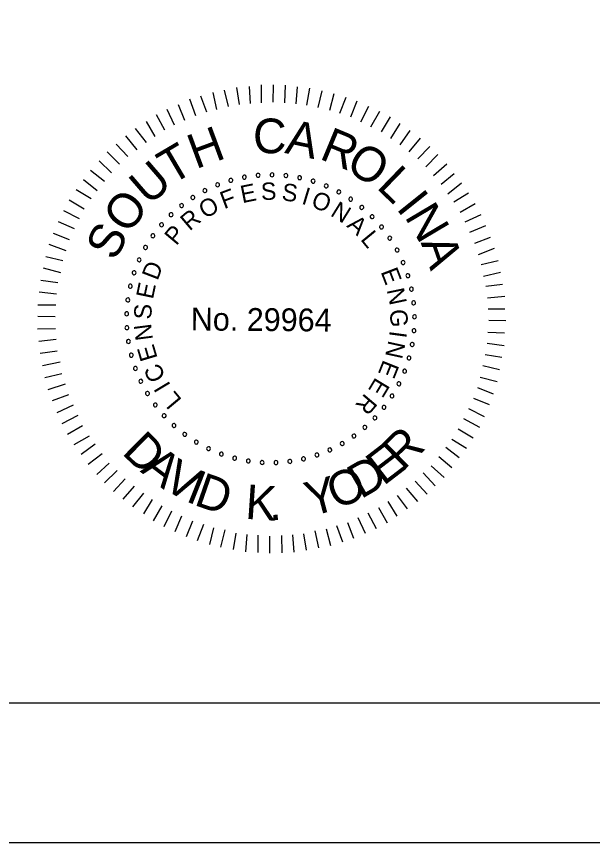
# Model space of a CAD drawing. Extents: x -125.5 to -89.3, y 42.4 to 64.4.
# Drawn here: x -102.136 to -100.072, y 42.449 to 45.407 of the extents above; entities that cross this region are included whole.
import ezdxf

# ---------------------------------------------------------------- set-up
doc = ezdxf.new("R2010")
doc.units = 0
for name, color, linetype in [('BR_BORDER LINES', 7, 'Continuous'), ('BR_TEXT', 7, 'Continuous'), ('Level 31', 7, 'Continuous')]:
    doc.layers.add(name, color=color, linetype=linetype)

msp = doc.modelspace()

# ---------------------------------------------------------------- linework, layer by layer
at = {"layer": 'BR_BORDER LINES'}
msp.add_line((-123.6994, 42.9486), (-90.0334, 42.9486), dxfattribs=at)
at = {"layer": 'BR_TEXT'}
for p, q in [((-101.3372, 45.0917), (-101.3461, 45.1527)), ((-101.2977, 45.0957), (-101.3015, 45.1567)), ((-101.2582, 45.098), (-101.2576, 45.1623)), ((-101.2161, 45.1002), (-101.2156, 45.162)), ((-101.1741, 45.0973), (-101.1718, 45.1616)), ((-101.1338, 45.0944), (-101.129, 45.1552)), ((-101.0952, 45.0897), (-101.0844, 45.1506)), ((-101.4541, 45.0644), (-101.476, 45.122)), ((-101.418, 45.0744), (-101.4312, 45.1354)), ((-101.3767, 45.0843), (-101.3908, 45.1437)), ((-101.0549, 45.0817), (-101.0407, 45.1408)), ((-101.0138, 45.071), (-100.9979, 45.1318)), ((-100.977, 45.0605), (-100.9551, 45.1177)), ((-101.5325, 45.035), (-101.556, 45.091)), ((-101.4937, 45.0518), (-101.5147, 45.1104)), ((-100.9376, 45.0472), (-100.9157, 45.1054)), ((-100.9017, 45.0298), (-100.8738, 45.0853)), ((-101.5695, 45.0181), (-101.5957, 45.0741)), ((-100.8658, 45.0123), (-100.8345, 45.0678)), ((-101.6394, 44.9767), (-101.6698, 45.031)), ((-101.604, 45.0004), (-101.6344, 45.0547)), ((-100.8282, 44.994), (-100.796, 45.0478)), ((-101.6704, 44.9555), (-101.7095, 45.0064)), ((-100.795, 44.9697), (-100.761, 45.0235)), ((-100.7617, 44.948), (-100.7252, 44.9983)), ((-101.7041, 44.93), (-101.744, 44.9801)), ((-100.7293, 44.922), (-100.6886, 44.9714)), ((-101.7369, 44.9054), (-101.7786, 44.9503)), ((-100.6977, 44.8968), (-100.6545, 44.941)), ((-101.7663, 44.8782), (-101.8106, 44.9223)), ((-100.6697, 44.8691), (-100.6264, 44.9125)), ((-101.7958, 44.8475), (-101.8392, 44.8899)), ((-100.6416, 44.838), (-100.594, 44.8796)), ((-101.8209, 44.816), (-101.8704, 44.855)), ((-101.8469, 44.7827), (-101.8964, 44.8226)), ((-100.6144, 44.806), (-100.5677, 44.8442)), ((-100.5906, 44.7723), (-100.5414, 44.8114)), ((-101.8686, 44.7537), (-101.9224, 44.7868)), ((-100.5686, 44.743), (-100.516, 44.7752)), ((-101.893, 44.717), (-101.9467, 44.7492)), ((-100.5466, 44.7059), (-100.4931, 44.7372)), ((-101.9104, 44.6828), (-101.9668, 44.7107)), ((-101.9279, 44.6461), (-101.9851, 44.6714)), ((-100.5288, 44.6714), (-100.4711, 44.6984)), ((-100.5111, 44.6344), (-100.4542, 44.6588)), ((-101.9454, 44.6076), (-102.0035, 44.6295)), ((-100.4943, 44.5956), (-100.4374, 44.6166)), ((-101.9577, 44.5674), (-102.0193, 44.5902)), ((-100.4809, 44.5552), (-100.4232, 44.577)), ((-101.97, 44.5314), (-102.0308, 44.5465)), ((-100.4708, 44.519), (-100.4107, 44.5331)), ((-101.9772, 44.4894), (-102.0397, 44.5054)), ((-100.4626, 44.4769), (-100.4024, 44.4919)), ((-101.9878, 44.4535), (-102.0487, 44.4617)), ((-100.4543, 44.4408), (-100.3951, 44.448)), ((-101.9925, 44.4123), (-102.0542, 44.4197)), ((-100.4478, 44.3996), (-100.3868, 44.4059)), ((-101.9954, 44.3729), (-102.0597, 44.3734)), ((-100.4464, 44.3601), (-100.3863, 44.3596)), ((-101.9974, 44.3317), (-102.06, 44.3322)), ((-100.4442, 44.3189), (-100.3833, 44.3184)), ((-101.9961, 44.2888), (-102.0604, 44.2876)), ((-100.4471, 44.276), (-100.3871, 44.2738)), ((-101.9938, 44.2501), (-102.0556, 44.2429)), ((-100.4492, 44.2374), (-100.3883, 44.2292)), ((-101.9898, 44.2089), (-102.0509, 44.2)), ((-101.9799, 44.1693), (-102.0426, 44.1561)), ((-100.4563, 44.1963), (-100.3972, 44.1863)), ((-100.4653, 44.1568), (-100.4053, 44.1426)), ((-101.9733, 44.1272), (-102.0344, 44.1131)), ((-100.4742, 44.1148), (-100.4143, 44.0998)), ((-101.9616, 44.0903), (-102.0236, 44.0693)), ((-101.95, 44.0515), (-102.0085, 44.0306)), ((-100.4848, 44.0781), (-100.4275, 44.0561)), ((-100.4989, 44.0396), (-100.4424, 44.0176)), ((-101.9331, 44.0145), (-101.9908, 43.9875)), ((-100.5163, 44.0028), (-100.4599, 43.9749)), ((-101.9162, 43.9783), (-101.9731, 43.9487)), ((-100.5346, 43.9669), (-100.4774, 43.9364)), ((-101.8994, 43.9413), (-101.9537, 43.91)), ((-101.8756, 43.9042), (-101.93, 43.8729)), ((-100.553, 43.9301), (-100.5, 43.898)), ((-101.8544, 43.8748), (-101.9045, 43.8383)), ((-100.5756, 43.8934), (-100.5235, 43.8612)), ((-100.5981, 43.8644), (-100.5495, 43.8271)), ((-101.829, 43.8411), (-101.8791, 43.8021)), ((-100.6224, 43.8312), (-100.5764, 43.7913)), ((-101.8043, 43.8075), (-101.8485, 43.7666)), ((-100.6502, 43.7979), (-100.6033, 43.7563)), ((-101.7754, 43.7815), (-101.8204, 43.7364)), ((-100.6787, 43.7724), (-100.6362, 43.7266)), ((-101.7465, 43.7512), (-101.7889, 43.7052)), ((-101.714, 43.7252), (-101.7548, 43.6783)), ((-100.7073, 43.7426), (-100.6648, 43.6959)), ((-101.6808, 43.6992), (-101.7207, 43.6514)), ((-100.7392, 43.7172), (-100.6993, 43.6696)), ((-101.6501, 43.6774), (-101.6814, 43.6254)), ((-100.8057, 43.6705), (-100.7727, 43.6179)), ((-100.772, 43.6917), (-100.7364, 43.6433)), ((-101.6151, 43.6549), (-101.6464, 43.6011)), ((-100.8393, 43.6485), (-100.808, 43.5941)), ((-101.5809, 43.6348), (-101.608, 43.5793)), ((-101.5442, 43.6174), (-101.5687, 43.5618)), ((-100.9134, 43.6122), (-100.8865, 43.5562)), ((-100.8773, 43.629), (-100.8468, 43.573)), ((-101.5057, 43.5999), (-101.5276, 43.5434)), ((-101.4663, 43.5876), (-101.4891, 43.5294)), ((-100.9892, 43.5836), (-100.9682, 43.5251)), ((-100.9496, 43.5953), (-100.9286, 43.5385)), ((-101.4304, 43.5752), (-101.4446, 43.5162)), ((-101.3892, 43.568), (-101.4044, 43.5064)), ((-101.3499, 43.5565), (-101.3598, 43.4983)), ((-101.3104, 43.552), (-101.3152, 43.4902)), ((-101.271, 43.549), (-101.2715, 43.4872)), ((-101.1869, 43.5484), (-101.1857, 43.4865)), ((-101.1465, 43.5506), (-101.1428, 43.4888)), ((-101.1079, 43.5545), (-101.098, 43.4961)), ((-101.0674, 43.5654), (-101.0542, 43.5035)), ((-101.0262, 43.5719), (-101.0112, 43.5126)), ((-101.229, 43.5461), (-101.2295, 43.4852))]:
    msp.add_line(p, q, dxfattribs=at)
for centre, start, end in [((-101.3681, 44.8202), 16.1422, 196.1422), ((-101.3681, 44.8202), 196.1422, 16.1422), ((-101.3196, 44.8316), 10.6038, 190.6038), ((-101.3196, 44.8316), 190.6038, 10.6038), ((-101.2702, 44.8383), 5.0653, 185.0653), ((-101.2702, 44.8383), 185.0653, 5.0653), ((-101.2204, 44.8402), 359.5268, 179.5268), ((-101.2204, 44.8402), 179.5268, 359.5268), ((-101.1707, 44.8373), 173.9884, 353.9884), ((-101.1707, 44.8373), 353.9884, 173.9884), ((-101.1214, 44.8296), 168.4499, 348.4499), ((-101.1214, 44.8296), 348.4499, 168.4499), ((-101.0732, 44.8172), 162.9114, 342.9114), ((-101.0732, 44.8172), 342.9114, 162.9114), ((-101.4607, 44.7836), 27.2191, 207.2191), ((-101.4153, 44.8042), 21.6807, 201.6807), ((-101.4153, 44.8042), 201.6807, 21.6807), ((-101.0263, 44.8002), 157.373, 337.373), ((-101.0263, 44.8002), 337.373, 157.373), ((-101.5039, 44.7588), 32.7576, 212.7576), ((-101.5039, 44.7588), 212.7576, 32.7576), ((-101.4607, 44.7836), 207.2191, 27.2191), ((-100.9814, 44.7787), 151.8345, 331.8345), ((-100.9814, 44.7787), 331.8345, 151.8345), ((-100.9387, 44.753), 326.2961, 146.2961), ((-101.5445, 44.7299), 38.2961, 218.2961), ((-101.5445, 44.7299), 218.2961, 38.2961), ((-100.9387, 44.753), 146.2961, 326.2961), ((-100.8987, 44.7233), 320.7576, 140.7576), ((-101.5821, 44.6973), 43.8345, 223.8345), ((-101.5821, 44.6973), 223.8345, 43.8345), ((-100.8987, 44.7233), 140.7576, 320.7576), ((-100.8617, 44.6899), 135.2191, 315.2191), ((-100.8617, 44.6899), 315.2191, 135.2191), ((-101.6164, 44.6611), 49.373, 229.373), ((-101.6164, 44.6611), 229.373, 49.373), ((-100.8281, 44.6531), 129.6807, 309.6807), ((-100.8281, 44.6531), 309.6807, 129.6807), ((-101.6471, 44.6218), 54.9114, 234.9114), ((-101.6471, 44.6218), 234.9114, 54.9114), ((-100.7983, 44.6132), 124.1422, 304.1422), ((-100.7983, 44.6132), 304.1422, 124.1422), ((-101.6738, 44.5798), 60.4499, 240.4499), ((-101.6738, 44.5798), 240.4499, 60.4499), ((-100.7724, 44.5706), 118.6038, 298.6038), ((-100.7724, 44.5706), 298.6038, 118.6038), ((-101.6964, 44.5354), 65.9884, 245.9884), ((-101.6964, 44.5354), 245.9884, 65.9884), ((-100.7508, 44.5257), 113.0653, 293.0653), ((-100.7508, 44.5257), 293.0653, 113.0653), ((-101.7145, 44.4889), 71.5268, 251.5268), ((-101.7145, 44.4889), 251.5268, 71.5268), ((-100.7336, 44.4789), 107.5268, 287.5268), ((-100.7336, 44.4789), 287.5268, 107.5268), ((-101.7281, 44.441), 77.0653, 257.0653), ((-101.7281, 44.441), 257.0653, 77.0653), ((-100.721, 44.4307), 101.9884, 281.9884), ((-100.721, 44.4307), 281.9884, 101.9884), ((-101.737, 44.392), 82.6038, 262.6038), ((-101.737, 44.392), 262.6038, 82.6038), ((-100.7131, 44.3815), 96.4499, 276.4499), ((-100.7131, 44.3815), 276.4499, 96.4499), ((-101.7411, 44.3423), 88.1422, 268.1422), ((-101.7411, 44.3423), 268.1422, 88.1422), ((-100.71, 44.3317), 90.9114, 270.9114), ((-100.71, 44.3317), 270.9114, 90.9114), ((-101.7404, 44.2925), 93.6807, 273.6807), ((-101.7404, 44.2925), 273.6807, 93.6807), ((-100.7118, 44.2819), 85.373, 265.373), ((-100.7118, 44.2819), 265.373, 85.373), ((-101.7349, 44.243), 99.2191, 279.2191), ((-101.7349, 44.243), 279.2191, 99.2191), ((-100.7183, 44.2325), 79.8345, 259.8345), ((-100.7183, 44.2325), 259.8345, 79.8345), ((-101.7246, 44.1942), 104.7576, 284.7576), ((-101.7246, 44.1942), 284.7576, 104.7576), ((-100.7295, 44.184), 74.2961, 254.2961), ((-100.7295, 44.184), 254.2961, 74.2961), ((-101.7097, 44.1466), 110.2961, 290.2961), ((-101.7097, 44.1466), 290.2961, 110.2961), ((-100.7454, 44.1368), 68.7576, 248.7576), ((-100.7454, 44.1368), 248.7576, 68.7576), ((-101.6903, 44.1008), 115.8345, 295.8345), ((-101.6903, 44.1008), 295.8345, 115.8345), ((-100.7658, 44.0913), 63.2191, 243.2191), ((-100.7658, 44.0913), 243.2191, 63.2191), ((-101.6665, 44.057), 121.373, 301.373), ((-101.6665, 44.057), 301.373, 121.373), ((-100.7904, 44.048), 57.6807, 237.6807), ((-100.7904, 44.048), 237.6807, 57.6807), ((-101.6386, 44.0157), 126.9114, 306.9114), ((-101.6386, 44.0157), 306.9114, 126.9114), ((-100.8192, 44.0073), 52.1422, 232.1422), ((-100.8192, 44.0073), 232.1422, 52.1422), ((-101.6069, 43.9773), 132.4499, 312.4499), ((-101.6069, 43.9773), 312.4499, 132.4499), ((-100.8517, 43.9695), 46.6038, 226.6038), ((-100.8517, 43.9695), 226.6038, 46.6038), ((-101.5716, 43.9421), 137.9884, 317.9884), ((-101.5716, 43.9421), 317.9884, 137.9884), ((-100.8877, 43.9351), 41.0653, 221.0653), ((-100.8877, 43.9351), 221.0653, 41.0653), ((-101.5331, 43.9105), 143.5268, 323.5268), ((-101.5331, 43.9105), 323.5268, 143.5268), ((-100.9269, 43.9043), 35.5268, 215.5268), ((-100.9269, 43.9043), 215.5268, 35.5268), ((-101.4917, 43.8827), 149.0653, 329.0653), ((-101.4917, 43.8827), 329.0653, 149.0653), ((-100.9688, 43.8774), 29.9884, 209.9884), ((-100.9688, 43.8774), 209.9884, 29.9884), ((-101.4478, 43.8591), 154.6038, 334.6038), ((-101.4478, 43.8591), 334.6038, 154.6038), ((-101.4018, 43.8399), 340.1422, 160.1422), ((-101.0595, 43.8364), 18.9114, 198.9114), ((-101.0132, 43.8547), 24.4499, 204.4499), ((-101.0132, 43.8547), 204.4499, 24.4499), ((-101.4018, 43.8399), 160.1422, 340.1422), ((-101.3542, 43.8251), 165.6807, 345.6807), ((-101.3542, 43.8251), 345.6807, 165.6807), ((-101.3054, 43.8151), 351.2191, 171.2191), ((-101.3054, 43.8151), 171.2191, 351.2191), ((-101.2559, 43.8097), 356.7576, 176.7576), ((-101.2061, 43.8092), 2.2961, 182.2961), ((-101.1564, 43.8135), 7.8345, 187.8345), ((-101.1564, 43.8135), 187.8345, 7.8345), ((-101.1074, 43.8226), 13.373, 193.373), ((-101.1074, 43.8226), 193.373, 13.373), ((-101.0595, 43.8364), 198.9114, 18.9114), ((-101.2559, 43.8097), 176.7576, 356.7576), ((-101.2061, 43.8092), 182.2961, 2.2961)]:
    msp.add_arc(centre, 0.00701, start, end, dxfattribs=at)
at = {"layer": 'Level 31'}
msp.add_lwpolyline([(-125.5328, 42.4486), (-89.5328, 42.4486), (-89.5328, 64.4486), (-125.5328, 64.4486)], close=True, dxfattribs=at)

# ---------------------------------------------------------------- texts
at = {"layer": 'BR_TEXT'}
for s, height, rotation, p in [('C', 0.1241, 359.5482, (-101.2889, 44.9178)), ('A', 0.1241, 348.1981, (-101.1775, 44.9186)), ('H', 0.1241, 20.3637, (-101.4933, 44.8595)), ('R', 0.1241, 337.4344, (-101.0542, 44.8987)), ('T', 0.1241, 30.4992, (-101.5812, 44.802)), ('O', 0.1239, 326.5869, (-100.962, 44.862)), ('U', 0.1241, 40.8022, (-101.6624, 44.7272)), ('L', 0.1241, 315.9488, (-100.8494, 44.7942)), ('F', 0.0622, 20.6127, (-101.392, 44.7166)), ('E', 0.0622, 11.4103, (-101.3269, 44.7383)), ('S', 0.0622, 2.208, (-101.2591, 44.7493)), ('S', 0.0622, 352.6608, (-101.1878, 44.7491)), ('I', 0.0622, 343.1136, (-101.1175, 44.7371)), ('O', 0.1241, 52.0267, (-101.7369, 44.6233)), ('O', 0.0622, 338.4392, (-101.0841, 44.727)), ('I', 0.1241, 308.6613, (-100.778, 44.7199)), ('O', 0.0622, 30.8477, (-101.4594, 44.6806)), ('N', 0.0622, 328.2042, (-101.0145, 44.6955)), ('N', 0.1241, 300.7037, (-100.7474, 44.6905)), ('R', 0.0622, 40.3949, (-101.5156, 44.6367)), ('A', 0.0622, 318.657, (-100.9555, 44.6555)), ('S', 0.1239, 63.2511, (-101.7823, 44.5277)), ('P', 0.0622, 49.9421, (-101.5636, 44.5841)), ('L', 0.0622, 309.4546, (-100.9057, 44.6082)), ('A', 0.1241, 289.4792, (-100.6882, 44.5975)), ('D', 0.0622, 69.0364, (-101.6306, 44.4589)), ('E', 0.0622, 291.049, (-100.8319, 44.4929)), ('E', 0.0622, 78.2388, (-101.6472, 44.3922)), ('N', 0.0622, 281.8466, (-100.8097, 44.4279)), ('S', 0.0622, 87.786, (-101.6529, 44.3212)), ('No. 29964', 0.08175, 359.5268, (-101.5117, 44.2828)), ('G', 0.0622, 272.2995, (-100.7979, 44.3576)), ('N', 0.0622, 97.3332, (-101.6467, 44.2502)), ('I', 0.0622, 262.4084, (-100.7983, 44.2837)), ('E', 0.0622, 106.5355, (-101.6297, 44.1836)), ('N', 0.0622, 257.7339, (-100.8028, 44.2491)), ('E', 0.0622, 248.1867, (-100.8209, 44.1802)), ('C', 0.0622, 116.4266, (-101.5998, 44.1161)), ('E', 0.0622, 238.9844, (-100.8488, 44.1174)), ('I', 0.0622, 121.1011, (-101.5818, 44.0862)), ('L', 0.0622, 129.9595, (-101.5411, 44.034)), ('R', 0.0622, 229.782, (-100.8865, 44.0599)), ('D', 0.1236, 315.4053, (-101.7616, 43.8434)), ('R', 0.1236, 44.5947, (-100.7507, 43.7779)), ('E', 0.1236, 37.5339, (-100.8213, 43.724)), ('A', 0.1236, 322.8377, (-101.695, 43.7778)), ('V', 0.1236, 330.5179, (-101.6178, 43.7196)), ('D', 0.1236, 30.1015, (-100.9022, 43.6771)), ('O', 0.1236, 22.4212, (-100.9915, 43.64)), ('I', 0.1236, 338.1981, (-101.5336, 43.6722)), ('D', 0.1236, 340.7995, (-101.5037, 43.6588)), ('Y', 0.1236, 14.8649, (-101.0833, 43.6155)), ('K', 0.1236, 356.098, (-101.3185, 43.6082)), ('.', 0.1236, 3.1588, (-101.2299, 43.6019))]:
    msp.add_text(s, height=height, rotation=rotation, dxfattribs=at).set_placement(p)

doc.saveas('drawing.dxf')
